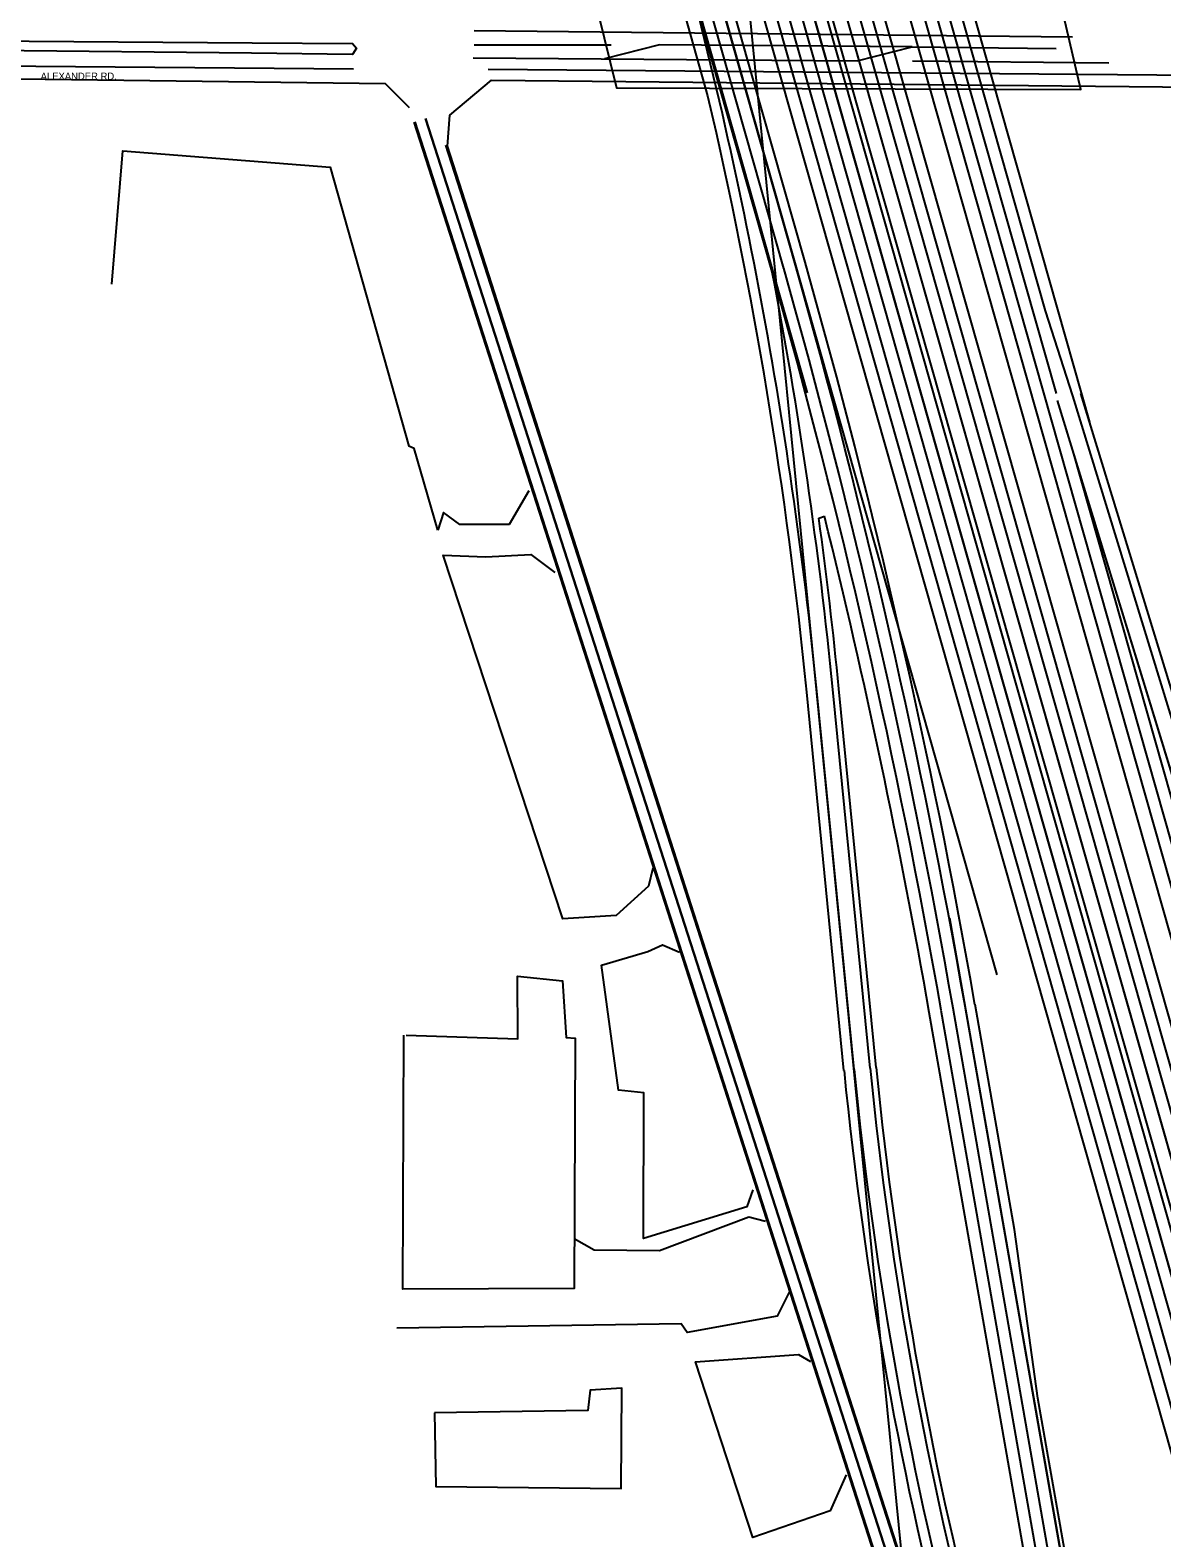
# Model space of a CAD drawing. Extents: x 227157 to 233208, y 434992 to 456232.
# Drawn here: x 228032 to 229152, y 438748 to 440241 of the extents above; entities that cross this region are included whole.
import ezdxf

# ---------------------------------------------------------------- set-up
doc = ezdxf.new("R2010")
doc.units = 0
for name, color, linetype in [('BD_X_Building', 7, 'Continuous'), ('BR_X_Slab_Object', 7, 'Continuous'), ('GE_X_Alignment', 7, 'Continuous'), ('PM_X_Edge_Line', 7, 'Continuous'), ('PM_X_Lane_Line', 7, 'Continuous'), ('PV_X_Curb', 7, 'Continuous'), ('PV_X_EOP', 7, 'Continuous'), ('SV_X_Text_Name', 7, 'Continuous')]:
    doc.layers.add(name, color=color, linetype=linetype)

msp = doc.modelspace()

# ---------------------------------------------------------------- linework, layer by layer
at = {"layer": 'BD_X_Building'}
msp.add_lwpolyline([(228404.1, 439246), (228514.6, 439242.2), (228514.2, 439304.5), (228558.9, 439299.8), (228562.6, 439243.8), (228571.2, 439243.1), (228570.2, 438995), (228400.7, 438994.5), (228401.6, 439246.1)], dxfattribs=at)
msp.add_lwpolyline([(228432.2, 438871.8), (228433.3, 438798.8), (228616.9, 438796.8), (228617.7, 438896.2), (228586.1, 438894.2), (228583.9, 438874.3)], close=True, dxfattribs=at)
at = {"layer": 'BR_X_Slab_Object'}
msp.add_lwpolyline([(228593.7, 440259.3), (228612.3, 440184.5), (229072.1, 440182.7), (229055.3, 440255.1)], close=True, dxfattribs=at)
at = {"layer": 'GE_X_Alignment'}
for p, q in [((229741.1, 437351.7), (227977.9, 443563.5)), ((229633.3, 437464.5), (227927.6, 443466.1)), ((227851.2, 443315.4), (228989, 439305.6)), ((229609.5, 437429.5), (227988.9, 443142.3)), ((228622.4, 440513.9), (228801.2, 439882.3)), ((228919.8, 438478), (228727.1, 440433.7)), ((228423.3, 440154.1), (229018.4, 438302.2)), ((229331.5, 438951.2), (229048.9, 439874.6)), ((228942.1, 439362.3), (229261.4, 437539.6))]:
    msp.add_line(p, q, dxfattribs=at)
for centre, radius, start, end in [((224290.9, 439141.4), 4541.6, 5.6268, 15.809), ((221754.9, 438012.8), 7312.2, 9.93754, 15.84131), ((232609.7, 439582.5), 3780.4, 185.6268, 204.1773)]:
    msp.add_arc(centre, radius, start, end, dxfattribs=at)
at = {"layer": 'PM_X_Edge_Line'}
for p, q in [((229405.2, 438534.9), (228394.3, 442096.5)), ((229504.8, 437916.6), (228327.5, 442058.8)), ((229527.9, 437923.2), (228350.6, 442065.3)), ((228263.8, 442041.2), (229294, 438409.6)), ((229328.7, 438419.5), (228298.5, 442051)), ((228789.4, 440008.8), (228216.7, 442027.3)), ((229037.1, 439963.6), (228452, 442025.2)), ((228766.4, 440002.2), (228193.6, 442020.7)), ((228471.5, 440227.1), (228607, 440226.8)), ((228905.5, 440211.2), (229099.9, 440209)), ((228979.3, 438387.7), (228412.8, 440150.7)), ((228989.8, 438391.1), (228423.3, 440154.1)), ((229000.3, 438394.5), (228443.4, 440127.6)), ((229064.2, 439879.2), (229037.1, 439963.6)), ((229191.8, 439407.6), (229048.9, 439874.6)), ((229207.1, 439412.3), (229064.2, 439879.2)), ((229428.3, 438541.5), (229064.3, 439824.1)), ((228863.4, 439213.4), (228826.5, 439588.3)), ((228847.5, 439211.8), (228810.5, 439586.7)), ((229071.8, 438621.8), (228957.4, 439274.7)), ((229048.2, 438617.7), (228933.8, 439270.5))]:
    msp.add_line(p, q, dxfattribs=at)
for points in [[(228251.5, 440228.9), (228351, 440228.2), (228355, 440223.8), (228351, 440217.5), (228251, 440218.6)], [(228470.4, 440214.1), (228850.7, 440211.1), (228904.9, 440224.8), (229047.6, 440223.2)], [(228904.9, 440224.8), (228654.8, 440227.1), (228600.5, 440213.1)]]:
    msp.add_lwpolyline(points, dxfattribs=at)
for centre, radius, start, end in [((224290.9, 439141.4), 4541.6, 5.6268, 15.809), ((221754.9, 438012.8), 7312.2, 9.93754, 15.84131), ((221754.9, 438012.8), 7288.2, 9.93754, 15.84131), ((224290.9, 439141.4), 4557.6, 5.6268, 10.8824), ((232609.7, 439582.5), 3780.4, 185.6268, 204.1773), ((232609.7, 439582.5), 3764.4, 185.6268, 204.1773)]:
    msp.add_arc(centre, radius, start, end, dxfattribs=at)
at = {"layer": 'PM_X_Lane_Line'}
for p, q in [((229416.8, 438538.2), (228405.8, 442099.8)), ((229047.9, 439881.6), (228417.4, 442103.1)), ((228339.1, 442062.1), (229516.3, 437919.9)), ((229305.6, 438412.9), (228275.4, 442044.5)), ((228286.9, 442047.7), (229317.1, 438416.2)), ((228777.9, 440005.5), (228205.2, 442024)), ((228471.5, 440241.3), (229063.8, 440235)), ((228351.9, 440202.7), (227162.9, 440212.8)), ((229659.1, 440192.6), (228485.1, 440202.5)), ((229060, 438619.8), (228945.6, 439272.6))]:
    msp.add_line(p, q, dxfattribs=at)
msp.add_arc((221754.9, 438012.8), 7300.2, 9.93754, 15.84131, dxfattribs=at)
at = {"layer": 'PV_X_Curb'}
msp.add_lwpolyline([(228251, 440218.6), (227993.6, 440221.3), (227982.4, 440224), (227986.1, 440230.8), (228251.5, 440228.9)], dxfattribs=at)
at = {"layer": 'PV_X_EOP'}
for p, q in [((229391.8, 438531.1), (228380.8, 442092.7)), ((229539.4, 437926.5), (228362.2, 442068.6)), ((229340.2, 438422.7), (228310, 442054.3)), ((229391.7, 438263.5), (228314.1, 442054.9)), ((229282.5, 438406.4), (228252.3, 442037.9)), ((229080.9, 439853.3), (228458.9, 442044.8)), ((228799.1, 440011.5), (228528.9, 440963.7)), ((228702.7, 440176.3), (228609.7, 440510.2)), ((228407.3, 440164.6), (228383.6, 440188.4)), ((228488.6, 440191.8), (229666.6, 440180.4)), ((228978.4, 438387.4), (228411.9, 440150.4)), ((229001.2, 438394.8), (228444.8, 440126.4)), ((229214.7, 439414.7), (229071.9, 439881.6)), ((228812.6, 439758.2), (228818.3, 439759.9)), ((228869.4, 439214), (228832.4, 439588.9)), ((228837.5, 439210.9), (228800.6, 439585.8)), ((229006.3, 439053.6), (228967.3, 439276.4)), ((229036.4, 438615.6), (228922, 439268.4)), ((229029.5, 438886.5), (229006.3, 439053.6)), ((229075.8, 438622.5), (229029.5, 438886.5))]:
    msp.add_line(p, q, dxfattribs=at)
for points in [[(228383.6, 440188.4), (227994.3, 440193.3), (227957, 440173.1), (227960.5, 440005.4)], [(228444.8, 440126.4), (228447.3, 440157.3), (228488.6, 440191.8)], [(228112.5, 439990), (228123.4, 440121.9), (228328.7, 440105.7), (228406.6, 439829.5)], [(228435.5, 439746.1), (228412.1, 439827.2), (228406.6, 439829.5)], [(228525.6, 439785.3), (228505.9, 439751.7), (228457.3, 439751.7), (228441, 439763.6), (228435.5, 439746.1)], [(228648.1, 439411.4), (228644, 439393.7), (228612, 439364.6), (228559.1, 439361.1), (228440.8, 439721.4), (228482.9, 439719.8), (228527.4, 439722.2), (228551.1, 439704.1)], [(228747.4, 439092.7), (228741.3, 439076), (228638.9, 439044.6), (228639.2, 439188.9), (228614.1, 439191.5), (228597.4, 439315.4), (228643.3, 439328.8), (228657.7, 439335.5), (228674.7, 439328.1)], [(228759.9, 439061.5), (228743.4, 439065.6), (228654.8, 439032.4), (228590.3, 439033), (228570.3, 439044.3)], [(228783.1, 438991.4), (228771.4, 438967.7), (228682.4, 438951.3), (228676.2, 438959.9), (228394.7, 438955.7)], [(228839.6, 438810.4), (228823.7, 438774.9), (228747.2, 438748.2), (228690.5, 438922.5), (228792.6, 438929.7), (228804.5, 438922.8)]]:
    msp.add_lwpolyline(points, dxfattribs=at)
for centre, radius, start, end in [((224290.9, 439141.4), 4531.6, 5.6268, 13.2003), ((221754.9, 438012.8), 7322.2, 9.93754, 15.84131), ((224290.9, 439141.4), 4563.6, 5.6268, 7.7673), ((221754.9, 438012.8), 7276.2, 9.93754, 13.89347), ((232609.7, 439582.5), 3790.4, 185.6268, 204.1773), ((232609.7, 439582.5), 3758.4, 185.6268, 204.1773)]:
    msp.add_arc(centre, radius, start, end, dxfattribs=at)

# ---------------------------------------------------------------- texts
at = {"layer": 'SV_X_Text_Name'}
msp.add_text('ALEXANDER RD.', height=7, dxfattribs=at).set_placement((228042.1, 440192.4))

doc.saveas('drawing.dxf')
